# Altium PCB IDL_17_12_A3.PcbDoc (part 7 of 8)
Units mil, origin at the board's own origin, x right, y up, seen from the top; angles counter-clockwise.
Board outline 5119.97 x 10350 mil, 6 copper layers (Top Signal, 3.3 Volt, GND, 5 Volt, Split Plane, Bot Signal), stack 66.2 mil thick; 510 components, 178 nets, 2317 pads, 385 vias.
Unrouted connection lines stored in the file: 1.
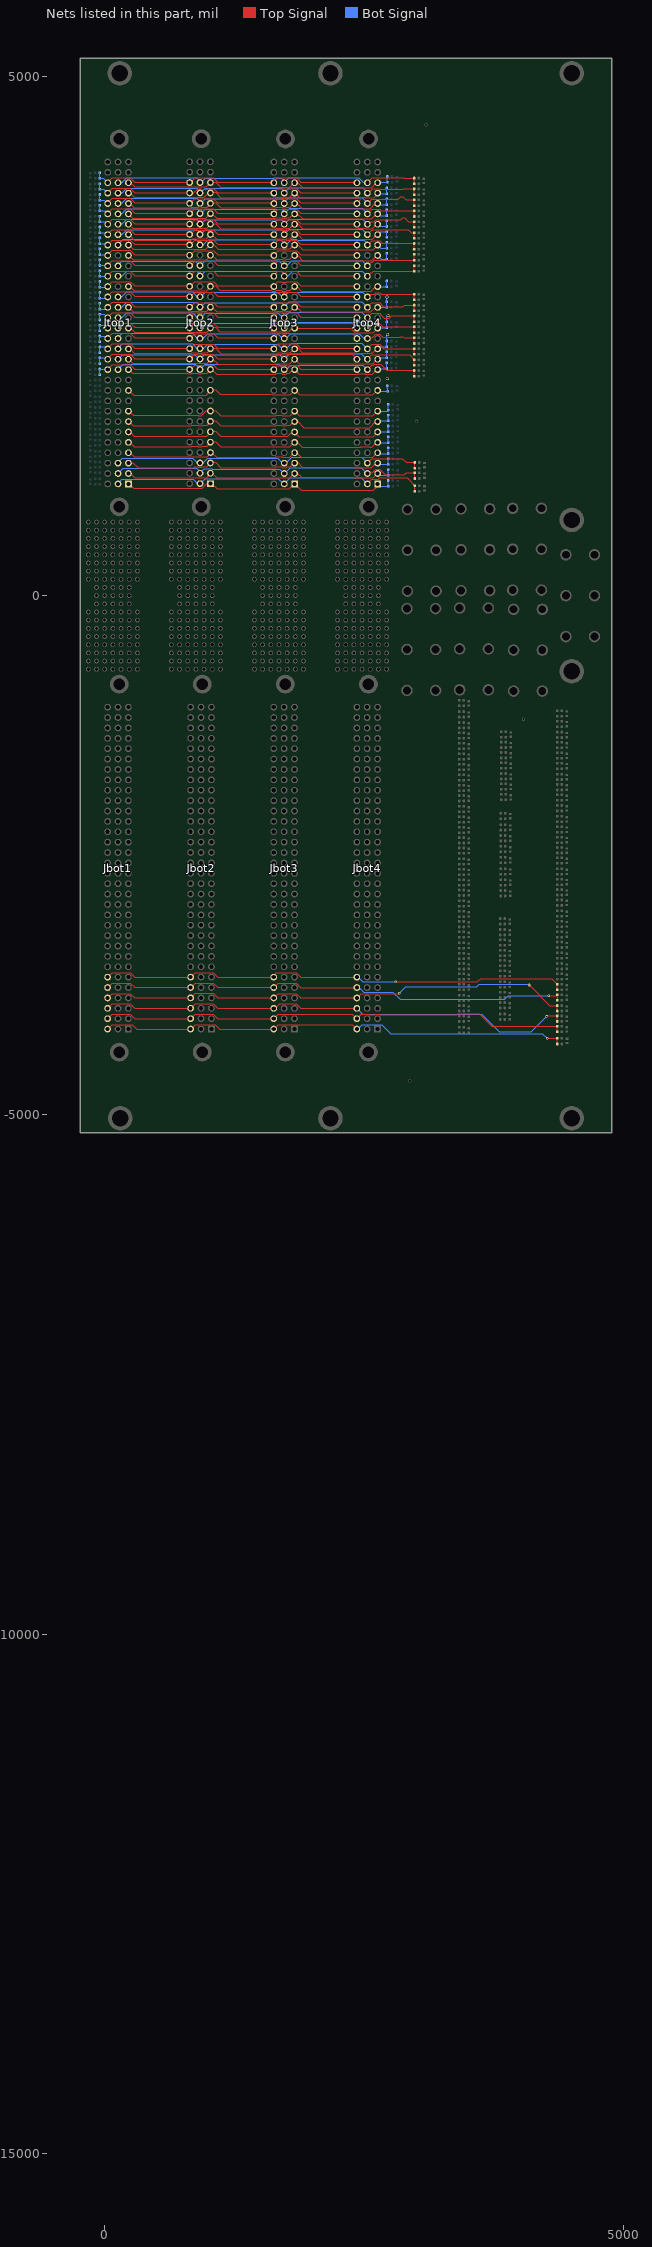
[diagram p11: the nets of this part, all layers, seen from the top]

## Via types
v1: diameter 25.59, hole 11.81, Top Signal to Bot Signal, 385 vias

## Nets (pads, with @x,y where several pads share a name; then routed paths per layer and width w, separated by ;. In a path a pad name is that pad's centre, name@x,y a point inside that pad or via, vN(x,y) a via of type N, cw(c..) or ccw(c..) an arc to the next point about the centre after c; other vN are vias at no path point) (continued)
JB84: Jbot1.C6 Jbot2.C6 Jbot3.C6 Jbot4.C6 R1RB_IDL_17_12_TerB84.1 R2RB_IDL_17_12_TerB84.2 | length 4543.9
  Top Signal w8: Jbot1.C6@28.26,-3673.77 70.74,-3631.29 245.86,-3631.29 287.92,-3673.35 Jbot2.C6@828.19,-3673.35 871.01,-3630.52 1045.44,-3630.52 1088.27,-3673.35 1608.49,-3673.35 1618.13,-3663.7 1650.55,-3631.29 1845.79,-3631.29 1888.27,-3673.77 Jbot4.C6@2428.19,-3673.77 ; v1(2802.08,-3719.17) 3550.2,-3719.17 3550.68,-3718.69 3586.72,-3718.69 3587.94,-3719.9 3620.16,-3687.68 3748.83,-3687.68 3749.35,-3688.2 4304.11,-3688.2 R1RB_IDL_17_12_TerB84.1@4358.16,-3742.25 4358.16,-3768.94 4358.67,-3769.46 R2RB_IDL_17_12_TerB84.2@4358.67,-3795.11
  Bot Signal w8: Jbot4.C6@2428.19,-3673.77 2442.94,-3673.77 2486.46,-3717.29 2800.2,-3717.29 v1(2802.08,-3719.17)
JB85: Jbot1.C5 Jbot2.C5 Jbot3.C5 Jbot4.C5 R1RB_IDL_17_12_TerB85.1 R2RB_IDL_17_12_TerB85.2 | length 4551
  Top Signal w8: Jbot1.C5@28.26,-3773.77 70.74,-3731.29 245.86,-3731.29 287.92,-3773.35 Jbot2.C5@828.19,-3773.35 870.67,-3730.87 1045.79,-3730.87 1088.27,-3773.35 1627.77,-3773.35 Jbot3.C5@1628.19,-3773.77 1670.67,-3731.29 1845.79,-3731.29 1888.27,-3773.77 Jbot4.C5@2428.19,-3773.77 ; v1(4275.93,-3852.46) R1RB_IDL_17_12_TerB85.1@4358.16,-3852.46 ; R1RB_IDL_17_12_TerB85.1@4358.16,-3842.25 R1RB_IDL_17_12_TerB85.1@4358.16,-3852.46 ; R2RB_IDL_17_12_TerB85.2@4358.67,-3895.11 4358.16,-3868.94 R1RB_IDL_17_12_TerB85.1@4358.16,-3852.46
  Bot Signal w8: Jbot4.C5@2428.19,-3773.77 2451.37,-3773.77 2497.23,-3819.62 2774.9,-3819.62 2844.07,-3888.8 3851.52,-3888.8 3887.86,-3852.46 v1(4275.93,-3852.46)
JB86: Jbot1.C4 Jbot2.C4 Jbot3.C4 Jbot4.C4 R1RB_IDL_17_12_TerB86.1 R2RB_IDL_17_12_TerB86.2 | length 4630.8
  Top Signal w8: Jbot1.C4@28.26,-3873.77 70.74,-3831.29 245.86,-3831.29 287.92,-3873.35 Jbot2.C4@828.19,-3873.35 870.67,-3830.87 1045.79,-3830.87 1088.27,-3873.35 1627.77,-3873.35 Jbot3.C4@1628.19,-3873.77 1670.67,-3831.29 1845.79,-3831.29 1888.27,-3873.77 Jbot4.C4@2428.19,-3873.77 2470.67,-3831.29 2834.4,-3831.29 v1(2836.02,-3829.66) ; v1(4087.23,-3750) 4100.68,-3763.46 4101.89,-3763.46 4285.68,-3947.25 R1RB_IDL_17_12_TerB86.1@4358.16,-3947.25 4358.16,-3973.94 4358.67,-3974.46 R2RB_IDL_17_12_TerB86.2@4358.67,-4000.11
  Bot Signal w8: v1(2836.02,-3829.66) 2836.02,-3827.35 2899.09,-3764.28 3582.92,-3764.28 3606.76,-3740.44 4077.66,-3740.44 v1(4087.23,-3750)
JB87: Jbot1.C3 Jbot2.C3 Jbot3.C3 Jbot4.C3 R1RB_IDL_17_12_TerB87.1 R2RB_IDL_17_12_TerB87.2 | length 4645
  Top Signal w8: Jbot1.C3@28.26,-3973.77 70.74,-3931.29 245.86,-3931.29 287.92,-3973.35 Jbot2.C3@828.19,-3973.35 870.67,-3930.87 1045.79,-3930.87 1088.27,-3973.35 1627.77,-3973.35 Jbot3.C3@1628.19,-3973.77 1642.67,-3973.77 1685.9,-3930.53 ; 1685.9,-3930.25 1844.68,-3930.25 ; 1844.68,-3930.18 1888.27,-3973.77 Jbot4.C3@2428.19,-3973.77 ; v1(4256.68,-4051.46) 4260.89,-4047.25 R1RB_IDL_17_12_TerB87.1@4358.16,-4047.25 4358.16,-4099.6 R2RB_IDL_17_12_TerB87.2@4358.67,-4100.11
  Bot Signal w8: Jbot4.C3@2428.19,-3973.77 2485.71,-4031.29 3631.64,-4031.29 3798.81,-4198.46 4109.68,-4198.46 v1(4256.68,-4051.46)
JB88: Jbot1.C2 Jbot2.C2 Jbot3.C2 Jbot4.C2 R1RB_IDL_17_12_TerB88.1 R2RB_IDL_17_12_TerB88.2 | length 4564.8
  Top Signal w8: Jbot1.C2@28.26,-4073.77 70.74,-4031.29 245.86,-4031.29 287.92,-4073.35 Jbot2.C2@828.19,-4073.35 870.67,-4030.87 1045.79,-4030.87 1088.27,-4073.35 1627.77,-4073.35 Jbot3.C2@1628.19,-4073.77 1670.67,-4031.29 2385.71,-4031.29 Jbot4.C2@2428.19,-4073.77 2470.67,-4031.29 2545.78,-4031.29 2548.82,-4034.32 2607.56,-4034.32 2610.59,-4031.29 2645.78,-4031.29 2648.82,-4034.32 3392.18,-4034.32 3401.98,-4024.51 3607.12,-4024.51 3729.86,-4147.25 R1RB_IDL_17_12_TerB88.1@4358.16,-4147.25 4358.16,-4173.94 4358.67,-4174.46 R2RB_IDL_17_12_TerB88.2@4358.67,-4200.11
JB89: Jbot1.C1 Jbot2.C1 Jbot3.C1 Jbot4.C1 R1RB_IDL_17_12_TerB89.1 R2RB_IDL_17_12_TerB89.2 | length 4564.4
  Top Signal w8: Jbot1.C1@28.26,-4173.77 70.74,-4131.29 264.88,-4131.29 306.94,-4173.35 Jbot2.C1@828.19,-4173.35 870.67,-4130.87 1064.81,-4130.87 1107.29,-4173.35 1627.77,-4173.35 Jbot3.C1@1628.19,-4173.77 1670.67,-4131.29 2385.71,-4131.29 Jbot4.C1@2428.19,-4173.77 ; v1(4261.68,-4262.25) R1RB_IDL_17_12_TerB89.1@4360.11,-4262.25 4360.11,-4290.42 ; R2RB_IDL_17_12_TerB89.2@4360.08,-4317.34 4360.08,-4290.46
  Bot Signal w8: Jbot4.C1@2428.19,-4173.77 2436.88,-4173.77 2479.36,-4131.29 2670.67,-4131.29 2755.84,-4216.46 4215.89,-4216.46 v1(4261.68,-4262.25)
JT1: Jtop1.A30 Jtop2.A30 Jtop3.A30 Jtop4.A30 R1R_IDL_17_12_TerA1.1 R2R_IDL_17_12_TerA1.2 | length 2671.5
  Top Signal w8: Jtop1.A30@228.79,3982.06 241.96,3982.06 288.16,3935.87 978.39,3935.87 1018.19,3975.66 Jtop2.A30@1018.19,3978.35 ; Jtop2.A30@1018.19,3982.48 1068.16,3982.48 1116.89,3933.76 1646.87,3933.76 1648.28,3935.16 1710.28,3935.16 1711.68,3933.76 1780.41,3933.76 Jtop3.A30@1826.02,3979.37 ; Jtop3.A30@1815.98,3979.37 Jtop3.A30@1826.02,3979.37 ; Jtop3.A30@1828.72,3982.06 Jtop3.A30@1826.02,3979.37 ; Jtop4.A30@2615.98,3973.83 2570.47,3928.31 1907.31,3928.31 1856.26,3979.37 Jtop3.A30@1826.02,3979.37
  Bot Signal w8: Jtop4.A30@2629.28,3976.24 2634.94,3981.9 R2R_IDL_17_12_TerA1.2@2723.46,3981.9 2722.58,3982.77 R1R_IDL_17_12_TerA1.1@2722.58,4036.92
JT2: Jtop1.A29 Jtop2.A29 Jtop3.A29 Jtop4.A29 R1R_IDL_17_12_TerA2.1 R2R_IDL_17_12_TerA2.2 | length 2662.6
  Top Signal w8: Jtop1.A29@228.79,3882.06 Jtop1.A29@229.28,3882.06 ; Jtop1.A29@229.28,3876.24 245.63,3876.24 286,3835.87 835.78,3835.87 837.4,3837.48 898.98,3837.48 900.59,3835.87 935.78,3835.87 937.4,3837.48 960.44,3837.48 1001.31,3878.35 Jtop2.A29@1018.19,3878.35 ; Jtop2.A29@1028.72,3882.48 1068.16,3882.48 1116.89,3833.76 1646.87,3833.76 1649.86,3836.75 1708.69,3836.75 1711.68,3833.76 1746.87,3833.76 1749.86,3836.75 1783.4,3836.75 1828.72,3882.06 1877.03,3833.76 2446.87,3833.76 2447.33,3834.21 2511.23,3834.21 2511.68,3833.76 2597.53,3833.76 Jtop4.A29@2639.15,3875.37
  Bot Signal w8: Jtop4.A29@2629.28,3876.24 2634.85,3870.66 R2R_IDL_17_12_TerA2.2@2718.46,3870.66 2717.58,3871.54 R1R_IDL_17_12_TerA2.1@2717.58,3925.68
JT3: Jtop1.A28 Jtop2.A28 Jtop3.A28 Jtop4.A28 R1R_IDL_17_12_TerA3.1 R2R_IDL_17_12_TerA3.2 | length 2692.8
  Top Signal w8: Jtop1.A28@228.79,3782.06 237.3,3782.06 283.5,3735.87 835.78,3735.87 839.92,3740 896.46,3740 900.59,3735.87 935.78,3735.87 939.92,3740 986.24,3740 1028.72,3782.48 1068.16,3782.48 1116.89,3733.76 1646.87,3733.76 1651.44,3738.32 1707.12,3738.32 1711.68,3733.76 1746.87,3733.76 1751.44,3738.32 1784.98,3738.32 Jtop3.A28@1828.72,3782.06 ; Jtop3.A28@1806.71,3782.46 1846.99,3782.46 1901.62,3727.83 2557.62,3727.83 Jtop4.A28@2606.71,3776.92 ; Jtop4.A28@2629.28,3776.24 Jtop4.A28@2639.94,3765.57
  Bot Signal w8: Jtop4.A28@2629.28,3776.24 2639.85,3765.66 R2R_IDL_17_12_TerA3.2@2718.46,3765.66 2718.46,3819.81 R1R_IDL_17_12_TerA3.1@2717.58,3820.68
JT4: Jtop1.A27 Jtop2.A27 Jtop3.A27 Jtop4.A27 R1R_IDL_17_12_TerA4.1 R2R_IDL_17_12_TerA4.2 | length 2680.8
  Top Signal w8: Jtop1.A27@228.79,3682.06 Jtop1.A27@229.28,3682.06 ; Jtop1.A27@229.28,3676.24 270.54,3634.97 974.81,3634.97 Jtop2.A27@1018.19,3678.35 ; Jtop2.A27@1028.72,3682.48 1077.45,3633.76 1646.87,3633.76 1650.52,3637.4 1708.04,3637.4 1711.68,3633.76 1746.87,3633.76 1750.52,3637.4 1784.06,3637.4 Jtop3.A27@1826.59,3679.93 ; Jtop3.A27@1815.66,3679.93 Jtop3.A27@1826.59,3679.93 ; Jtop3.A27@1828.72,3682.06 Jtop3.A27@1826.59,3679.93 ; Jtop4.A27@2615.66,3674.39 2570.25,3628.98 1906.89,3628.98 1855.94,3679.93 Jtop3.A27@1826.59,3679.93 ; Jtop4.A27@2629.28,3676.24 Jtop4.A27@2644.94,3660.57
  Bot Signal w8: Jtop4.A27@2629.28,3676.24 2644.85,3660.66 R2R_IDL_17_12_TerA4.2@2718.46,3660.66 2718.46,3714.81 R1R_IDL_17_12_TerA4.1@2717.58,3715.68
JT5: Jtop1.A26 Jtop2.A26 Jtop3.A26 Jtop4.A26 R1R_IDL_17_12_TerA5.1 R2R_IDL_17_12_TerA5.2 | length 2704.3
  Top Signal w8: Jtop1.A26@228.79,3582.06 Jtop1.A26@229.28,3582.06 ; Jtop1.A26@229.28,3576.24 269.65,3535.87 835.78,3535.87 838.26,3538.34 898.12,3538.34 900.59,3535.87 982.1,3535.87 1028.72,3582.48 1068.16,3582.48 1116.89,3533.76 1646.87,3533.76 1650.85,3537.73 1707.71,3537.73 1711.68,3533.76 1746.87,3533.76 1750.85,3537.73 1784.39,3537.73 Jtop3.A26@1828.72,3582.06 ; Jtop3.A26@1819.89,3583.13 1860.17,3583.13 1909.54,3533.76 2446.87,3533.76 2449.11,3535.99 2509.44,3535.99 2511.68,3533.76 2576.06,3533.76 Jtop4.A26@2619.89,3577.59 ; Jtop4.A26@2629.28,3576.24 Jtop4.A26@2649.94,3555.57
  Bot Signal w8: Jtop4.A26@2629.28,3576.24 2649.85,3555.66 R2R_IDL_17_12_TerA5.2@2718.46,3555.66 2718.46,3609.81 R1R_IDL_17_12_TerA5.1@2717.58,3610.68
JT6: Jtop1.A25 Jtop2.A25 Jtop3.A25 Jtop4.A25 R1R_IDL_17_12_TerA6.1 R2R_IDL_17_12_TerA6.2 | length 2685.1
  Top Signal w8: Jtop1.A25@228.79,3482.06 231.95,3478.91 290.99,3419.86 291.95,3420.83 834.76,3420.83 849.8,3435.87 935.78,3435.87 937.07,3437.15 977,3437.15 Jtop2.A25@1018.19,3478.35 ; Jtop2.A25@1028.72,3482.48 1077.45,3433.76 1646.87,3433.76 1651.93,3438.81 1706.63,3438.81 1711.68,3433.76 1746.87,3433.76 1751.93,3438.81 1785.47,3438.81 Jtop3.A25@1826.93,3480.27 ; Jtop3.A25@1816.87,3480.27 Jtop3.A25@1826.93,3480.27 ; Jtop3.A25@1828.72,3482.06 Jtop3.A25@1826.93,3480.27 ; Jtop4.A25@2616.87,3474.73 2575.9,3433.76 1903.66,3433.76 1857.15,3480.27 Jtop3.A25@1826.93,3480.27 ; Jtop4.A25@2629.28,3476.24 Jtop4.A25@2635.77,3469.75
  Bot Signal w8: Jtop4.A25@2629.28,3476.24 2658.72,3505.68 R1R_IDL_17_12_TerA6.1@2717.58,3505.68 2717.58,3451.54 R2R_IDL_17_12_TerA6.2@2718.46,3450.66
JT7: Jtop1.A24 Jtop2.A24 Jtop3.A24 Jtop4.A24 R1R_IDL_17_12_TerA7.1 R2R_IDL_17_12_TerA7.2 | length 2699.8
  Top Signal w8: Jtop1.A24@228.79,3382.06 274.99,3335.87 975.71,3335.87 Jtop2.A24@1018.19,3378.35 1018.19,3371.95 1028.72,3382.48 1044.58,3382.48 1093.31,3333.76 1646.87,3333.76 1652.76,3339.64 1705.8,3339.64 1711.68,3333.76 1746.87,3333.76 1752.76,3339.64 1786.3,3339.64 Jtop3.A24@1827.7,3381.04 ; Jtop3.A24@1818.68,3381.04 Jtop3.A24@1827.7,3381.04 ; Jtop3.A24@1828.72,3382.06 Jtop3.A24@1827.7,3381.04 ; Jtop4.A24@2629.28,3376.24 2584.05,3331.01 1909,3331.01 1858.96,3381.04 Jtop3.A24@1827.7,3381.04
  Bot Signal w8: Jtop4.A24@2629.28,3376.24 2659.85,3345.66 R2R_IDL_17_12_TerA7.2@2718.46,3345.66 2717.58,3346.54 R1R_IDL_17_12_TerA7.1@2717.58,3400.68
JT8: Jtop1.A23 Jtop2.A23 Jtop3.A23 Jtop4.A23 R1R_IDL_17_12_TerA8.1 R2R_IDL_17_12_TerA8.2 | length 2714.9
  Top Signal w8: Jtop1.A23@228.79,3282.06 274.99,3235.87 835.78,3235.87 836.16,3236.25 900.21,3236.25 900.59,3235.87 982.1,3235.87 1028.72,3282.48 1077.45,3233.76 1646.87,3233.76 1651.09,3237.97 1707.47,3237.97 1711.68,3233.76 1746.87,3233.76 1751.09,3237.97 1784.63,3237.97 Jtop3.A23@1824.24,3277.58 ; Jtop3.A23@1817.47,3277.58 Jtop3.A23@1824.24,3277.58 ; Jtop3.A23@1828.72,3282.06 Jtop3.A23@1824.24,3277.58 ; Jtop4.A23@2641.02,3295.59 2572.07,3226.63 1908.7,3226.63 1857.75,3277.58 Jtop3.A23@1824.24,3277.58
  Bot Signal w8: Jtop4.A23@2629.28,3276.24 2664.85,3240.66 R2R_IDL_17_12_TerA8.2@2718.46,3240.66 2718.46,3267.09 2717.58,3267.97 R1R_IDL_17_12_TerA8.1@2717.58,3295.68
JT9: Jtop1.A20 Jtop2.A20 Jtop3.A20 Jtop4.A20 R1R_IDL_17_12_TerA9.1 R2R_IDL_17_12_TerA9.2 | length 2668.1
  Top Signal w8: Jtop1.A20@228.79,2982.06 238.83,2982.06 285.02,2935.87 835.78,2935.87 837.51,2937.59 898.87,2937.59 900.59,2935.87 935.78,2935.87 937.51,2937.59 983.83,2937.59 1028.72,2982.48 1068.16,2982.48 1109.69,2940.95 1604.49,2940.95 1611.68,2933.76 1646.87,2933.76 1654.07,2940.95 1704.49,2940.95 1711.68,2933.76 1746.87,2933.76 1754.07,2940.95 1787.61,2940.95 Jtop3.A20@1825.96,2979.3 ; Jtop3.A20@1807.79,2979.3 Jtop3.A20@1825.96,2979.3 ; Jtop3.A20@1828.72,2982.06 Jtop3.A20@1825.96,2979.3 ; Jtop4.A20@2607.79,2973.76 2566.59,2932.55 1894.82,2932.55 1848.07,2979.3 Jtop3.A20@1825.96,2979.3 ; Jtop4.A20@2629.28,2976.24 Jtop4.A20@2629.94,2975.57
  Bot Signal w8: Jtop4.A20@2629.28,2976.24 2629.85,2975.66 R2R_IDL_17_12_TerA9.2@2718.46,2975.66 2718.46,3002.09 2717.58,3002.97 R1R_IDL_17_12_TerA9.1@2717.58,3030.68
JT10: AS.1 Jtop1.A18 Jtop2.A18 Jtop3.A18 Jtop4.A18 R1R_IDL_17_12_TerA10.1 R2R_IDL_17_12_TerA10.2 | length 2713
  Top Signal w8: Jtop1.A18@228.79,2782.06 274.99,2735.87 835.78,2735.87 836.67,2736.76 899.7,2736.76 900.59,2735.87 935.78,2735.87 936.67,2736.76 982.99,2736.76 1028.72,2782.48 1077.45,2733.76 1646.87,2733.76 1652.99,2739.87 1705.57,2739.87 1711.68,2733.76 1746.87,2733.76 1752.99,2739.87 1786.53,2739.87 Jtop3.A18@1826.9,2780.24 ; Jtop3.A18@1805.37,2780.24 Jtop3.A18@1826.9,2780.24 ; Jtop3.A18@1828.72,2782.06 Jtop3.A18@1826.9,2780.24 ; Jtop4.A18@2605.37,2774.7 2564.43,2733.76 2511.68,2733.76 2510,2735.44 2448.56,2735.44 2446.87,2733.76 1892.14,2733.76 1845.65,2780.24 Jtop3.A18@1826.9,2780.24 ; Jtop4.A18@2629.28,2776.24 Jtop4.A18@2629.94,2775.57
  Bot Signal w8: Jtop4.A18@2629.28,2776.24 2629.85,2775.66 R2R_IDL_17_12_TerA10.2@2718.46,2775.66 2718.46,2802.09 2717.58,2802.97 R1R_IDL_17_12_TerA10.1@2717.58,2830.68 AS.1@2717.58,2875.93
JT11: DTACK.1 Jtop1.A16 Jtop2.A16 Jtop3.A16 Jtop4.A16 R1R_IDL_17_12_TerA11.1 R2R_IDL_17_12_TerA11.2 | length 2739.3
  Top Signal w8: Jtop1.A16@228.79,2582.06 242.31,2582.06 288.51,2535.87 835.78,2535.87 835.94,2536.02 900.44,2536.02 900.59,2535.87 982.1,2535.87 1028.72,2582.48 1069,2582.48 1108.96,2542.52 1602.92,2542.52 1611.68,2533.76 1646.87,2533.76 1655.64,2542.52 1702.92,2542.52 1711.68,2533.76 1746.87,2533.76 1754.83,2541.71 1771.16,2541.71 1805.69,2576.24 2367.9,2576.24 2412.85,2531.29 2584.33,2531.29 Jtop4.A16@2633.62,2580.57
  Bot Signal w8: Jtop4.A16@2629.28,2576.24 2633.7,2580.66 R2R_IDL_17_12_TerA11.2@2718.46,2580.66 2717.58,2581.54 R1R_IDL_17_12_TerA11.1@2717.58,2635.68 2717.58,2684.07 DTACK.1@2729.61,2696.1
JT12: Jtop1.A14 Jtop2.A14 Jtop3.A14 Jtop4.A14 R1R_IDL_17_12_TerA12.1 R2R_IDL_17_12_TerA12.2 WRITE.1 | length 2754.2
  Top Signal w8: Jtop1.A14@228.79,2382.06 239.95,2382.06 286.15,2335.87 835.78,2335.87 839.92,2340 896.46,2340 900.59,2335.87 935.78,2335.87 939.92,2340 986.24,2340 1028.72,2382.48 1069,2382.48 1120.52,2330.97 1657.83,2330.97 1666.44,2339.58 1705.86,2339.58 1711.68,2333.76 1746.87,2333.76 1752.7,2339.58 1786.24,2339.58 Jtop3.A14@1828.72,2382.06 ; Jtop3.A14@1818.29,2385.05 1858.56,2385.05 1904.03,2339.58 2405.86,2339.58 2411.68,2333.76 2446.87,2333.76 2449.84,2336.72 2508.72,2336.72 2511.68,2333.76 2567,2333.76 2574.31,2341.07 2579.84,2341.07 Jtop4.A14@2618.29,2379.51 ; Jtop4.A14@2629.28,2376.24 Jtop4.A14@2633.47,2380.43
  Bot Signal w8: Jtop4.A14@2629.28,2376.24 2650.49,2397.45 R2R_IDL_17_12_TerA12.2@2718.09,2397.45 2717.22,2398.32 R1R_IDL_17_12_TerA12.1@2717.22,2452.47 2717.22,2506.2 WRITE.1@2724.12,2513.11
JT13: Jtop1.A13 Jtop2.A13 Jtop3.A13 Jtop4.A13 R1R_IDL_17_12_TerA13.1 R2R_IDL_17_12_TerA13.2 | length 2684.7
  Top Signal w8: Jtop1.A13@228.79,2282.06 270.85,2240 796.46,2240 800.59,2235.87 835.78,2235.87 839.92,2240 896.46,2240 900.59,2235.87 935.78,2235.87 939.92,2240 986.24,2240 1028.72,2282.48 1038.36,2282.48 1091.54,2229.3 1646.32,2229.3 1650.77,2233.76 1780.41,2233.76 Jtop3.A13@1826.09,2279.43 ; Jtop3.A13@1829.28,2276.24 1872.53,2232.99 2581.09,2232.99 Jtop4.A13@2623,2274.9 ; Jtop4.A13@2629.28,2276.24 Jtop4.A13@2645.4,2292.36
  Bot Signal w8: Jtop4.A13@2629.28,2276.24 2645.49,2292.45 R2R_IDL_17_12_TerA13.2@2718.09,2292.45 2717.22,2293.32 R1R_IDL_17_12_TerA13.1@2717.22,2347.47
JT14: Jtop1.A12 Jtop2.A12 Jtop3.A12 Jtop4.A12 R1R_IDL_17_12_TerA14.1 R2R_IDL_17_12_TerA14.2 | length 2688.5
  Top Signal w8: Jtop1.A12@228.79,2182.06 270.85,2140 796.46,2140 800.59,2135.87 835.78,2135.87 839.92,2140 896.46,2140 900.59,2135.87 935.78,2135.87 939.92,2140 986.24,2140 1028.72,2182.48 1077.45,2133.76 1646.87,2133.76 1653.34,2140.22 1705.22,2140.22 1711.68,2133.76 1746.87,2133.76 1753.34,2140.22 1779.44,2140.22 1815.46,2176.24 Jtop3.A12@1829.28,2176.24 1871.76,2133.76 2446.87,2133.76 2449.86,2136.74 2508.7,2136.74 2511.68,2133.76 2578.6,2133.76 Jtop4.A12@2623,2178.16 ; Jtop3.A12@1823,2183.7 Jtop3.A12@1829.28,2183.7 ; Jtop4.A12@2629.28,2176.24 Jtop4.A12@2640.4,2187.36
  Bot Signal w8: Jtop4.A12@2629.28,2176.24 2640.49,2187.45 R2R_IDL_17_12_TerA14.2@2718.09,2187.45 2718.09,2214.09 2717.22,2214.97 R1R_IDL_17_12_TerA14.1@2717.22,2242.47
JT15: Jtop1.A10 Jtop2.A10 Jtop3.A10 Jtop4.A10 R1R_IDL_17_12_TerA15.1 R2R_IDL_17_12_TerA15.2 SYSCLK.1 | length 2678.9
  Top Signal w8: Jtop1.A10@228.79,1982.06 280.9,1929.96 976.19,1929.96 1028.72,1982.48 1069,1982.48 1111.9,1939.58 1605.86,1939.58 1611.68,1933.76 1787.73,1933.76 1832.38,1978.41 1878.1,1932.69 2583.61,1932.69 Jtop4.A10@2623.79,1972.87 ; Jtop4.A10@2629.28,1976.24 Jtop4.A10@2638.1,1967.42
  Bot Signal w8: Jtop4.A10@2629.28,1976.24 2638.01,1967.51 R2R_IDL_17_12_TerA15.2@2724.1,1967.51 2724.1,1994.09 2723.22,1994.97 R1R_IDL_17_12_TerA15.1@2723.22,2022.53
JT16: Jtop1.A8 Jtop2.A8 Jtop3.A8 Jtop4.A8 R1R_IDL_17_12_TerA16.1 R2R_IDL_17_12_TerA16.2 | length 2680
  Top Signal w8: Jtop1.A8@228.79,1782.06 274.99,1735.87 900.53,1735.87 ; 900.56,1735.9 901.63,1734.83 934.75,1734.83 ; 935.78,1735.87 978.27,1778.35 Jtop2.A8@1018.19,1778.35 ; Jtop2.A8@1018.19,1782.48 1069,1782.48 1117.73,1733.76 1646.87,1733.76 1652.68,1739.56 1705.88,1739.56 1711.68,1733.76 1786.77,1733.76 Jtop3.A8@1829.28,1776.26 ; Jtop3.A8@1823,1776.26 Jtop3.A8@1829.28,1776.26 ; Jtop3.A8@1826.09,1779.43 Jtop3.A8@1828.72,1782.06 ; Jtop4.A8@2623,1770.72 2583.21,1730.93 2554.46,1730.93 2552.67,1732.72 2505.88,1732.72 2504.09,1730.93 1874.62,1730.93 Jtop3.A8@1829.28,1776.26
  Bot Signal w8: Jtop4.A8@2629.28,1776.24 2719.23,1776.24 R2R_IDL_17_12_TerA16.2@2729.8,1786.8 2728.92,1787.68 R1R_IDL_17_12_TerA16.1@2728.92,1841.82
JT17: Jtop1.A7 Jtop2.A7 Jtop3.A7 Jtop4.A7 R1R_IDL_17_12_TerA17.1 R2R_IDL_17_12_TerA17.2 | length 2722.9
  Top Signal w8: Jtop1.A7@228.79,1682.06 274.99,1635.87 835.78,1635.87 839.23,1639.31 897.15,1639.31 900.59,1635.87 935.78,1635.87 939.92,1640 986.24,1640 1028.72,1682.48 1069,1682.48 1117.73,1633.76 1646.87,1633.76 1652.68,1639.56 1705.88,1639.56 1711.68,1633.76 1746.87,1633.76 1752.68,1639.56 1786.21,1639.56 Jtop3.A7@1828.72,1682.06 ; Jtop3.A7@1811.99,1682.66 1852.27,1682.66 1916.34,1618.59 2411.56,1618.59 2411.68,1618.72 2446.87,1618.72 2447,1618.59 2511.56,1618.59 2511.68,1618.72 2546.87,1618.72 2547,1618.59 2553.46,1618.59 Jtop4.A7@2611.99,1677.12 ; Jtop4.A7@2629.28,1676.24 Jtop4.A7@2648.1,1695.05
  Bot Signal w8: Jtop4.A7@2629.28,1676.24 2636.85,1683.8 R2R_IDL_17_12_TerA17.2@2729.8,1683.8 2729.8,1710.76 2728.92,1711.64 R1R_IDL_17_12_TerA17.1@2728.92,1738.82
JT18: Jtop1.A6 Jtop2.A6 Jtop3.A6 Jtop4.A6 R1R_IDL_17_12_TerA18.1 R2R_IDL_17_12_TerA18.2 | length 2683.1
  Top Signal w8: Jtop1.A6@228.79,1582.06 241.05,1582.06 287.24,1535.87 835.78,1535.87 836.53,1536.61 899.85,1536.61 900.59,1535.87 982.1,1535.87 1028.72,1582.48 1069,1582.48 1117.73,1533.76 1646.87,1533.76 1649.36,1536.24 1709.2,1536.24 1711.68,1533.76 1764.22,1533.76 1806.7,1576.24 Jtop3.A6@1829.28,1576.24 ; Jtop3.A6@1828.72,1574.12 1871.2,1531.64 2586.06,1531.64 Jtop4.A6@2623,1568.58 ; Jtop4.A6@2629.28,1576.24 Jtop4.A6@2643.1,1590.05
  Bot Signal w8: Jtop4.A6@2629.28,1576.24 2631.85,1578.8 R2R_IDL_17_12_TerA18.2@2729.8,1578.8 2729.8,1605.76 2728.92,1606.64 R1R_IDL_17_12_TerA18.1@2728.92,1633.82
JT19: Jtop1.A5 Jtop2.A5 Jtop3.A5 Jtop4.A5 R1R_IDL_17_12_TerA19.1 R2R_IDL_17_12_TerA19.2 | length 2690.3
  Top Signal w8: Jtop1.A5@228.79,1482.06 236.94,1482.06 283.13,1435.87 835.78,1435.87 839.92,1440 896.46,1440 900.59,1435.87 935.78,1435.87 939.92,1440 986.24,1440 1028.72,1482.48 1069,1482.48 1117.73,1433.76 1646.87,1433.76 1647.9,1434.78 1710.66,1434.78 1711.68,1433.76 1780.41,1433.76 Jtop3.A5@1824.03,1477.37 ; Jtop3.A5@1815.14,1477.37 Jtop3.A5@1824.03,1477.37 ; Jtop3.A5@1828.72,1482.06 Jtop3.A5@1824.03,1477.37 ; Jtop4.A5@2615.14,1471.83 2573.96,1430.66 2554.73,1430.66 2552.67,1432.72 2465.96,1432.72 2463.9,1430.66 1902.13,1430.66 1855.42,1477.37 Jtop3.A5@1824.03,1477.37 ; Jtop4.A5@2629.28,1476.24 Jtop4.A5@2638.1,1485.05
  Bot Signal w8: Jtop4.A5@2629.28,1476.24 2631.71,1473.8 R2R_IDL_17_12_TerA19.2@2729.8,1473.8 2729.8,1500.76 2728.92,1501.64 R1R_IDL_17_12_TerA19.1@2728.92,1528.82
JT20: Jtop1.A4 Jtop2.A4 Jtop3.A4 Jtop4.A4 R1R_IDL_17_12_TerA20.1 R2R_IDL_17_12_TerA20.2 | length 2685.1
  Top Signal w8: Jtop1.A4@228.79,1382.06 238.26,1382.06 284.45,1335.87 835.78,1335.87 839.92,1340 896.46,1340 900.59,1335.87 935.78,1335.87 939.92,1340 986.24,1340 1028.72,1382.48 1077.45,1333.76 1646.87,1333.76 1648.66,1335.54 1709.9,1335.54 1711.68,1333.76 1780.41,1333.76 Jtop3.A4@1817.06,1370.4 ; Jtop3.A4@1814.35,1370.4 Jtop3.A4@1817.06,1370.4 ; Jtop3.A4@1828.72,1382.06 Jtop3.A4@1817.06,1370.4 ; Jtop4.A4@2614.35,1364.86 2583.01,1333.52 1891.52,1333.52 1854.63,1370.4 Jtop3.A4@1817.06,1370.4 ; Jtop4.A4@2629.28,1376.24 Jtop4.A4@2639.43,1386.39
  Bot Signal w8: Jtop4.A4@2629.28,1376.24 2636.71,1368.8 R2R_IDL_17_12_TerA20.2@2729.8,1368.8 2729.8,1422.95 R1R_IDL_17_12_TerA20.1@2728.92,1423.82
JT21: Jtop1.A3 Jtop2.A3 Jtop3.A3 Jtop4.A3 R1R_IDL_17_12_TerA21.1 R2R_IDL_17_12_TerA21.2 | length 2697.3
  Top Signal w8: Jtop1.A3@228.79,1282.06 269.07,1282.06 321.24,1229.89 856.33,1229.89 865.4,1238.96 897.5,1238.96 900.59,1235.87 935.78,1235.87 938.88,1238.96 985.2,1238.96 1028.72,1282.48 1069,1282.48 1117.73,1233.76 1646.87,1233.76 1654.16,1241.04 1704.4,1241.04 1711.68,1233.76 1746.87,1233.76 1752.7,1239.58 1786.24,1239.58 Jtop3.A3@1828.72,1282.06 ; Jtop3.A3@1816.71,1283.88 1856.99,1283.88 1902.33,1238.54 2392.04,1238.54 2400.72,1229.86 2568.23,1229.86 Jtop4.A3@2616.71,1278.34 ; Jtop4.A3@2629.28,1276.24 Jtop4.A3@2630.46,1275.05
  Bot Signal w8: Jtop4.A3@2629.28,1276.24 2641.71,1263.8 R2R_IDL_17_12_TerA21.2@2729.8,1263.8 2729.8,1290.76 2728.92,1291.64 R1R_IDL_17_12_TerA21.1@2728.92,1318.82
JT22: Jtop1.A2 Jtop2.A2 Jtop3.A2 Jtop4.A2 R1R_IDL_17_12_TerA22.1 R2R_IDL_17_12_TerA22.2 | length 2699.8
  Top Signal w8: Jtop1.A2@228.79,1182.06 243.29,1182.06 289.49,1135.87 835.78,1135.87 836.21,1136.29 900.16,1136.29 900.59,1135.87 982.1,1135.87 1028.72,1182.48 1077.69,1133.52 1780.18,1133.52 Jtop3.A2@1828.72,1182.06 ; Jtop3.A2@1810.42,1184.78 1850.7,1184.78 1896.93,1138.54 2392.04,1138.54 2396.83,1133.76 2586.8,1133.76 Jtop4.A2@2629.28,1176.24
  Bot Signal w8: Jtop4.A2@2629.28,1176.24 2646.71,1158.8 R2R_IDL_17_12_TerA22.2@2729.8,1158.8 2729.8,1185.76 2728.92,1186.64 R1R_IDL_17_12_TerA22.1@2728.92,1213.82
JT23: Jtop1.A1 Jtop2.A1 Jtop3.A1 Jtop4.A1 R1R_IDL_17_12_TerA23.1 R2R_IDL_17_12_TerA23.2 | length 2699.7
  Top Signal w8: Jtop1.A1@228.79,1082.06 229.21,1082.48 279.33,1032.36 938.68,1032.36 988.8,1082.48 1028.72,1082.48 1082.18,1029.03 1775.69,1029.03 Jtop3.A1@1826.09,1079.43 ; Jtop3.A1@1829.28,1076.24 1892.21,1013.3 2587.64,1013.3 Jtop4.A1@2624.58,1050.24 ; Jtop4.A1@2629.28,1076.24 Jtop4.A1@2640.46,1065.05
  Bot Signal w8: Jtop4.A1@2629.28,1076.24 2651.71,1053.8 R2R_IDL_17_12_TerA23.2@2729.8,1053.8 2729.8,1080.76 2728.92,1081.64 R1R_IDL_17_12_TerA23.1@2728.92,1108.82
JT24: Jtop1.B30 Jtop2.B30 Jtop3.B30 Jtop4.B30 R1R_IDL_17_12_TerA24.1 R2R_IDL_17_12_TerA24.2 | length 3061.5
  Top Signal w8: Jtop4.B30@2540.26,3976.24 Jtop4.B30@2529.28,3976.24 2575.93,4022.88 2877.81,4022.88 2879.33,4021.36 R1R_IDL_17_12_TerA24.1@2981.11,4021.36 2981.11,3993.65 2981.99,3992.77 R2R_IDL_17_12_TerA24.2@2981.99,3966.34
  Bot Signal w8: Jtop1.B30@128.79,3982.06 168.72,3982.06 211.2,4024.54 810.71,4024.54 811.13,4024.96 846.32,4024.96 846.74,4024.54 886.66,4024.54 928.72,3982.48 967.98,4021.74 1630.11,4021.74 ; 1630.53,4022.16 1665.73,4022.16 1666.15,4021.74 1706.07,4021.74 Jtop3.B30@1737.24,3990.58 ; Jtop3.B30@1728.72,3982.06 Jtop3.B30@1737.24,3990.58 ; Jtop3.B30@1748.13,3979.68 Jtop3.B30@1737.24,3990.58 ; Jtop4.B30@2528.72,3982.06 2488.8,3982.06 2446.32,4024.54 1771.2,4024.54 Jtop3.B30@1737.24,3990.58
JT25: Jtop1.B29 Jtop2.B29 Jtop3.B29 Jtop4.B29 R1R_IDL_17_12_TerA25.1 R2R_IDL_17_12_TerA25.2 | length 3039.7
  Top Signal w8: Jtop4.B29@2529.28,3876.24 2538.19,3876.24 2580.67,3918.72 2646.87,3918.72 2652.33,3913.27 2870.73,3913.27 2873.83,3916.36 R1R_IDL_17_12_TerA25.1@2981.11,3916.36 2981.11,3862.22 R2R_IDL_17_12_TerA25.2@2981.99,3861.34
  Bot Signal w8: Jtop1.B29@128.79,3882.06 168.72,3882.06 211.2,3924.54 810.71,3924.54 811.13,3924.96 846.32,3924.96 846.74,3924.54 886.66,3924.54 928.72,3882.48 967.98,3921.74 1630.11,3921.74 ; 1630.53,3922.16 1706.07,3922.16 ; 1706.07,3921.74 Jtop3.B29@1738.43,3889.39 ; Jtop3.B29@1728.72,3882.06 1731.1,3882.06 Jtop3.B29@1738.43,3889.39 ; Jtop4.B29@2528.72,3882.06 2483.94,3926.85 1775.88,3926.85 Jtop3.B29@1738.43,3889.39
JT26: Jtop1.B28 Jtop2.B28 Jtop3.B28 Jtop4.B28 R1R_IDL_17_12_TerA26.1 R2R_IDL_17_12_TerA26.2 | length 3061
  Top Signal w8: Jtop4.B28@2529.28,3776.24 2571.76,3818.72 2827.11,3818.72 2851.5,3843.11 2870.38,3843.11 2902.12,3811.36 R1R_IDL_17_12_TerA26.1@2981.11,3811.36 2981.11,3783.65 2981.99,3782.77 R2R_IDL_17_12_TerA26.2@2981.99,3756.34
  Bot Signal w8: Jtop1.B28@128.79,3782.06 168.72,3782.06 211.2,3824.54 810.71,3824.54 811.13,3824.96 846.32,3824.96 846.74,3824.54 886.66,3824.54 928.72,3782.48 967.98,3821.74 1630.11,3821.74 ; 1630.53,3822.16 1665.73,3822.16 1666.15,3821.74 1706.07,3821.74 Jtop3.B28@1735.2,3792.61 ; Jtop3.B28@1728.72,3782.06 1728.72,3786.13 Jtop3.B28@1735.2,3792.61 ; Jtop4.B28@2528.72,3782.06 2479.54,3831.24 1773.84,3831.24 Jtop3.B28@1735.2,3792.61
JT27: Jtop1.B27 Jtop2.B27 Jtop3.B27 Jtop4.B27 R1R_IDL_17_12_TerA27.1 R2R_IDL_17_12_TerA27.2 | length 3047.4
  Top Signal w8: Jtop4.B27@2529.28,3676.24 2571.76,3718.72 2646.87,3718.72 2659.23,3706.36 R1R_IDL_17_12_TerA27.1@2981.11,3706.36 2981.11,3678.65 2981.99,3677.77 R2R_IDL_17_12_TerA27.2@2981.99,3651.34
  Bot Signal w8: Jtop1.B27@128.79,3682.06 168.72,3682.06 211.2,3724.54 810.71,3724.54 811.13,3724.96 846.32,3724.96 846.74,3724.54 886.66,3724.54 928.72,3682.48 967.98,3721.74 1630.11,3721.74 ; 1630.53,3722.16 1665.73,3722.16 1666.15,3721.74 1706.07,3721.74 Jtop3.B27@1739.5,3688.32 ; Jtop3.B27@1728.72,3682.06 1733.24,3682.06 Jtop3.B27@1739.5,3688.32 ; Jtop4.B27@2528.72,3682.06 2478.57,3732.22 1783.4,3732.22 Jtop3.B27@1739.5,3688.32
JT28: Jtop1.B26 Jtop2.B26 Jtop3.B26 Jtop4.B26 R1R_IDL_17_12_TerA28.1 R2R_IDL_17_12_TerA28.2 | length 3059.4
  Top Signal w8: Jtop4.B26@2529.28,3576.24 2554.41,3601.36 2594.33,3601.36 2611.68,3618.72 2851.74,3618.72 2869.92,3636.9 2888.81,3636.9 2924.34,3601.36 R1R_IDL_17_12_TerA28.1@2981.11,3601.36 2981.99,3600.49 R2R_IDL_17_12_TerA28.2@2981.99,3546.34
  Bot Signal w8: Jtop1.B26@128.79,3582.06 168.72,3582.06 211.2,3624.54 810.71,3624.54 811.13,3624.96 846.32,3624.96 846.74,3624.54 886.66,3624.54 928.72,3582.48 967.98,3621.74 1630.11,3621.74 ; 1630.53,3622.16 1665.73,3622.16 1666.15,3621.74 1706.07,3621.74 Jtop3.B26@1739.69,3588.12 ; Jtop3.B26@1728.72,3582.06 1733.63,3582.06 Jtop3.B26@1739.69,3588.12 ; Jtop4.B26@2528.72,3582.06 2485.1,3625.69 1777.25,3625.69 Jtop3.B26@1739.69,3588.12
JT29: Jtop1.B25 Jtop2.B25 Jtop3.B25 Jtop4.B25 R1R_IDL_17_12_TerA29.1 R2R_IDL_17_12_TerA29.2 | length 3065.3
  Top Signal w8: Jtop4.B25@2529.28,3476.24 2572.8,3519.76 2581.86,3519.76 2585.12,3523.01 2924.12,3523.01 2950.77,3496.36 R1R_IDL_17_12_TerA29.1@2981.11,3496.36 2981.11,3468.65 2981.99,3467.77 R2R_IDL_17_12_TerA29.2@2981.99,3441.34
  Bot Signal w8: Jtop1.B25@128.79,3482.06 168.72,3482.06 211.62,3524.96 846.32,3524.96 847.16,3524.12 887.09,3524.12 928.72,3482.48 968.4,3522.16 1665.73,3522.16 1666.57,3521.32 1706.49,3521.32 Jtop3.B25@1737.24,3490.58 ; Jtop3.B25@1728.72,3482.06 Jtop3.B25@1737.24,3490.58 ; Jtop3.B25@1748.13,3479.68 Jtop3.B25@1737.24,3490.58 ; Jtop4.B25@2528.72,3482.06 2481.69,3529.09 1775.75,3529.09 Jtop3.B25@1737.24,3490.58
JT30: Jtop1.B24 Jtop2.B24 Jtop3.B24 Jtop4.B24 R1R_IDL_17_12_TerA30.1 R2R_IDL_17_12_TerA30.2 | length 3097
  Top Signal w8: Jtop4.B24@2529.28,3376.24 2571.76,3418.72 2646.87,3418.72 2674.23,3391.36 R1R_IDL_17_12_TerA30.1@2981.11,3391.36 2981.11,3363.65 2981.99,3362.77 R2R_IDL_17_12_TerA30.2@2981.99,3336.34 2962.03,3336.34
  Bot Signal w8: Jtop1.B24@128.79,3382.06 177.8,3431.07 874.76,3431.07 923.35,3382.48 Jtop2.B24@928.72,3382.48 ; Jtop2.B24@948.2,3379.26 997.21,3428.28 1694.17,3428.28 1742.76,3379.68 Jtop3.B24@1748.13,3379.68 ; Jtop3.B24@1756.8,3388.51 1805.81,3437.52 1807.92,3437.52 1811.68,3433.76 1846.88,3433.76 1858.28,3422.35 2498.83,3422.35 2537.11,3384.07 Jtop4.B24@2544.49,3376.69 ; Jtop4.B24@2529.28,3376.24 Jtop4.B24@2556.3,3376.24
JT31: Jtop1.B22 Jtop2.B22 Jtop3.B22 Jtop4.B22 R1R_IDL_17_12_TerA31.1 R2R_IDL_17_12_TerA31.2 | length 3054.4
  Top Signal w8: Jtop4.B22@2529.28,3176.24 2565.68,3212.63 2577.87,3212.63 2596.58,3231.34 R2R_IDL_17_12_TerA31.2@2981.99,3231.34 2981.99,3257.77 2981.11,3258.65 R1R_IDL_17_12_TerA31.1@2981.11,3286.36
  Bot Signal w8: Jtop1.B22@129.28,3176.24 129.28,3185.24 166.25,3222.2 874.33,3222.2 Jtop2.B22@918.19,3178.35 966.64,3226.8 1678.72,3226.8 Jtop3.B22@1729.28,3176.24 1754.32,3176.24 1802.58,3224.5 2481.02,3224.5 Jtop4.B22@2529.28,3176.24
JT32: Jtop1.B21 Jtop2.B21 Jtop3.B21 Jtop4.B21 R1R_IDL_17_12_TerA32.1 R2R_IDL_17_12_TerA32.2 | length 3050.9
  Top Signal w8: Jtop4.B21@2529.28,3076.24 2563.59,3110.54 2575.61,3110.54 2588.41,3123.34 R2R_IDL_17_12_TerA32.2@2981.99,3123.34 2981.11,3124.22 R1R_IDL_17_12_TerA32.1@2981.11,3178.36
  Bot Signal w8: Jtop1.B21@128.79,3082.06 168.72,3082.06 211.2,3124.54 810.71,3124.54 811.13,3124.96 886.24,3124.96 928.72,3082.48 967.98,3121.74 1630.11,3121.74 ; 1630.53,3122.16 1705.65,3122.16 Jtop3.B21@1745.75,3082.06 ; Jtop3.B21@1728.72,3082.06 Jtop3.B21@1745.75,3082.06 ; Jtop3.B21@1748.13,3079.68 Jtop3.B21@1745.75,3082.06 ; Jtop4.B21@2528.72,3082.06 2524.48,3082.06 2482,3124.54 1811.13,3124.54 1768.65,3082.06 Jtop3.B21@1745.75,3082.06
JT33: Jtop1.B19 Jtop2.B19 Jtop3.B19 Jtop4.B19 R1R_IDL_17_12_TerA33.1 R2R_IDL_17_12_TerA33.2 | length 3081.9
  Top Signal w8: Jtop4.B19@2529.28,2876.24 2556.41,2903.36 2596.33,2903.36 2611.68,2918.72 2646.87,2918.72 2662.23,2903.36 R1R_IDL_17_12_TerA33.1@2981.11,2903.36 2981.11,2849.22 R2R_IDL_17_12_TerA33.2@2981.99,2848.34
  Bot Signal w8: Jtop1.B19@128.79,2882.06 168.72,2882.06 211.2,2924.54 810.71,2924.54 811.13,2924.96 846.32,2924.96 888.8,2882.48 928.72,2882.48 967.98,2921.74 1630.11,2921.74 ; 1630.53,2922.16 1665.73,2922.16 1708.21,2879.68 Jtop3.B19@1748.13,2879.68 ; Jtop3.B19@1728.72,2882.06 1770.04,2923.38 2431.11,2923.38 2432.87,2921.62 2484.12,2921.62 2516.81,2888.93 2541.98,2888.93 Jtop4.B19@2529.28,2876.24
JT34: Jtop1.B18 Jtop2.B18 Jtop3.B18 Jtop4.B18 R1R_IDL_17_12_TerA34.1 R2R_IDL_17_12_TerA34.2 | length 3090.6
  Top Signal w8: Jtop4.B18@2529.28,2776.24 2571.76,2818.72 2646.87,2818.72 2684.3,2781.29 2872.81,2781.29 2889.88,2798.36 R1R_IDL_17_12_TerA34.1@2981.11,2798.36 2981.11,2770.65 2981.99,2769.77 R2R_IDL_17_12_TerA34.2@2981.99,2743.34
  Bot Signal w8: Jtop1.B18@128.79,2782.06 168.72,2782.06 211.2,2824.54 810.71,2824.54 811.13,2824.96 846.32,2824.96 846.74,2824.54 886.66,2824.54 928.72,2782.48 967.98,2821.74 1630.11,2821.74 ; 1630.53,2822.16 1665.73,2822.16 ; 1666.15,2821.74 1706.07,2821.74 Jtop3.B18@1737.24,2790.58 ; Jtop3.B18@1728.72,2782.06 Jtop3.B18@1737.24,2790.58 ; 2438.72,2830.99 1777.65,2830.99 Jtop3.B18@1737.24,2790.58 ; 2439.14,2831.41 2474.33,2831.41 ; 2474.75,2830.99 Jtop4.B18@2529.51,2776.24 ; Jtop4.B18@2529.28,2776.24 Jtop4.B18@2529.51,2776.24 ; Jtop4.B18@2557.49,2776.24 Jtop4.B18@2529.51,2776.24
JT35: Jtop1.B17 Jtop2.B17 Jtop3.B17 Jtop4.B17 R1R_IDL_17_12_TerA35.1 R2R_IDL_17_12_TerA35.2 | length 3127.7
  Top Signal w8: Jtop4.B17@2517.2,2689.59 2515.93,2689.59 Jtop4.B17@2529.28,2676.24 2571.76,2718.72 2646.87,2718.72 2694.49,2671.1 2739.97,2671.1 2762.23,2693.36 R1R_IDL_17_12_TerA35.1@2981.11,2693.36 2981.99,2692.49 R2R_IDL_17_12_TerA35.2@2981.99,2638.34 R2R_IDL_17_12_TerA35.2@2973.61,2629.97
  Bot Signal w8: Jtop1.B17@128.79,2682.06 168.72,2682.06 211.2,2724.54 810.71,2724.54 811.13,2724.96 846.32,2724.96 888.8,2682.48 928.72,2682.48 967.98,2721.74 1630.11,2721.74 ; 1630.53,2722.16 1665.73,2722.16 1708.21,2679.68 Jtop3.B17@1748.13,2679.68 ; Jtop3.B17@1728.72,2682.06 1777.65,2730.99 2438.72,2730.99 ; 2439.14,2731.41 2474.33,2731.41 Jtop4.B17@2536.77,2668.97
JT36: Jtop1.B16 Jtop2.B16 Jtop3.B16 Jtop4.B16 R1R_IDL_17_12_TerA36.1 R2R_IDL_17_12_TerA36.2 | length 3009.9
  Top Signal w8: Jtop4.B16@2529.28,2576.24 2571.76,2618.72 2646.87,2618.72 2677.23,2588.36 R1R_IDL_17_12_TerA36.1@2981.11,2588.36 2981.99,2587.49 R2R_IDL_17_12_TerA36.2@2981.99,2533.34 2978.56,2536.77 R2R_IDL_17_12_TerA36.2@2977.36,2535.58
  Bot Signal w8: Jtop1.B16@128.79,2582.06 171.69,2624.96 846.32,2624.96 888.8,2582.48 Jtop2.B16@928.72,2582.48 ; Jtop2.B16@948.2,2579.26 991.1,2622.16 1665.73,2622.16 1708.21,2579.68 Jtop3.B16@1748.13,2579.68 ; Jtop3.B16@1756.8,2588.51 1799.7,2631.41 2474.33,2631.41 Jtop4.B16@2516.81,2588.93
JT37: Jtop1.B15 Jtop2.B15 Jtop3.B15 Jtop4.B15 R1R_IDL_17_12_TerA37.1 R2R_IDL_17_12_TerA37.2 | length 3021.1
  Top Signal w8: Jtop4.B15@2529.28,2476.24 2536.41,2483.36 2576.33,2483.36 2611.68,2518.72 2646.87,2518.72 2677.48,2488.11 2846.98,2488.11 2853.56,2494.68 2872.44,2494.68 2883.76,2483.36 R1R_IDL_17_12_TerA37.1@2981.11,2483.36 2981.11,2429.22 R2R_IDL_17_12_TerA37.2@2981.99,2428.34 R2R_IDL_17_12_TerA37.2@2981.99,2427.77
  Bot Signal w8: Jtop1.B15@128.79,2482.06 171.69,2524.96 846.32,2524.96 888.8,2482.48 Jtop2.B15@928.72,2482.48 ; Jtop2.B15@948.2,2479.26 991.1,2522.16 1665.73,2522.16 1708.21,2479.68 Jtop3.B15@1748.13,2479.68 ; Jtop3.B15@1756.8,2488.51 1790.01,2521.72 2452.74,2521.72 2498.23,2476.24 Jtop4.B15@2529.28,2476.24
JT38: Jtop1.B14 Jtop2.B14 Jtop3.B14 Jtop4.B14 R1R_IDL_17_12_TerA38.1 R2R_IDL_17_12_TerA38.2 | length 3050.6
  Top Signal w8: Jtop4.B14@2529.28,2376.24 2571.76,2418.72 2646.87,2418.72 2687.23,2378.36 R1R_IDL_17_12_TerA38.1@2981.11,2378.36 2981.11,2350.65 2981.99,2349.77 R2R_IDL_17_12_TerA38.2@2981.99,2323.34
  Bot Signal w8: Jtop1.B14@128.79,2382.06 171.69,2424.96 846.32,2424.96 888.8,2382.48 Jtop2.B14@928.72,2382.48 ; Jtop2.B14@948.2,2379.26 991.1,2422.16 1665.73,2422.16 1708.21,2379.68 Jtop3.B14@1748.13,2379.68 ; Jtop3.B14@1756.8,2388.51 1799.7,2431.41 2474.33,2431.41 2516.81,2388.93 2541.98,2388.93 Jtop4.B14@2529.28,2376.24
JT39: Jtop1.B13 Jtop2.B13 Jtop3.B13 Jtop4.B13 R1R_IDL_17_12_TerA39.1 R2R_IDL_17_12_TerA39.2 | length 3064.7
  Top Signal w8: Jtop4.B13@2529.28,2276.24 2571.79,2318.74 2935.73,2318.74 R1R_IDL_17_12_TerA39.1@2981.11,2273.36 2981.11,2245.65 2981.99,2244.77 R2R_IDL_17_12_TerA39.2@2981.99,2218.34
  Bot Signal w8: Jtop1.B13@129.28,2276.24 174.04,2321 867.56,2321 910.21,2278.35 Jtop2.B13@918.19,2278.35 960.67,2320.83 1684.69,2320.83 Jtop3.B13@1729.28,2276.24 1784.08,2331.03 2471.19,2331.03 2520.2,2282.02 2520.2,2276.24 Jtop4.B13@2529.28,2276.24
JT40: Jtop1.B12 Jtop2.B12 Jtop3.B12 Jtop4.B12 R1R_IDL_17_12_TerA40.1 R2R_IDL_17_12_TerA40.2 | length 3086.7
  Top Signal w8: Jtop4.B12@2529.28,2176.24 2572.03,2218.99 2586.89,2218.99 2594.31,2226.41 2657.61,2226.41 2715.66,2168.36 R1R_IDL_17_12_TerA40.1@2981.11,2168.36 2981.99,2167.49 2981.12,2113.36 R2R_IDL_17_12_TerA40.2@2981.11,2112.68
  Bot Signal w8: Jtop1.B12@129.28,2176.24 179.58,2226.54 870,2226.54 Jtop2.B12@918.19,2178.35 968.48,2228.64 1676.88,2228.64 Jtop3.B12@1729.28,2176.24 1747.1,2176.24 1790.82,2219.95 2485.56,2219.95 Jtop4.B12@2529.28,2176.24 Jtop4.B12@2543.7,2176.24
JT41: Jtop1.B3 Jtop2.B3 Jtop3.B3 Jtop4.B3 R1R_IDL_17_12_TerA41.1 R2R_IDL_17_12_TerA41.2 | length 3011.5
  Top Signal w8: Jtop4.B3@2529.28,1276.24 2571.76,1318.72 2867.99,1318.72 2903.87,1282.84 R1R_IDL_17_12_TerA41.1@2987.01,1282.84 2987.01,1255.12 2987.89,1254.25 R2R_IDL_17_12_TerA41.2@2987.89,1227.82
  Bot Signal w8: Jtop1.B3@128.79,1282.06 171.69,1324.96 846.32,1324.96 888.8,1282.48 Jtop2.B3@928.72,1282.48 ; Jtop2.B3@948.2,1279.26 991.1,1322.16 1665.73,1322.16 1708.21,1279.68 Jtop3.B3@1748.13,1279.68 ; Jtop3.B3@1756.8,1288.51 1799.7,1331.41 2474.33,1331.41 Jtop4.B3@2516.81,1288.93
JT42: Jtop1.B2 Jtop2.B2 Jtop3.B2 Jtop4.B2 R1R_IDL_17_12_TerA42.1 R2R_IDL_17_12_TerA42.2 | length 3108.3
  Top Signal w8: Jtop4.B2@2529.28,1176.24 2535.88,1182.84 2575.8,1182.84 2611.68,1218.72 2646.87,1218.72 2700.63,1164.97 2884.15,1164.97 2902.02,1182.84 R1R_IDL_17_12_TerA42.1@2987.01,1182.84 2987.01,1155.12 2987.89,1154.25 R2R_IDL_17_12_TerA42.2@2987.89,1127.82
  Bot Signal w8: Jtop1.B2@129.28,1176.24 180.84,1227.8 884.6,1227.8 918.19,1194.21 Jtop2.B2@918.19,1178.35 960.67,1220.83 1035.79,1220.83 1037.15,1219.46 1686.05,1219.46 Jtop3.B2@1729.28,1176.24 1786.8,1233.76 2471.76,1233.76 Jtop4.B2@2529.28,1176.24 Jtop4.B2@2529.28,1189.3
JT43: Jtop1.B1 Jtop2.B1 Jtop3.B1 Jtop4.B1 R1R_IDL_17_12_TerA43.1 R2R_IDL_17_12_TerA43.2 | length 3099.7
  Top Signal w8: Jtop4.B1@2529.28,1076.24 2572.8,1119.76 2632.87,1119.76 2647.65,1134.53 2912.27,1134.53 R1R_IDL_17_12_TerA43.1@2986.94,1059.87 2986.94,1032.15 2987.81,1031.28 R2R_IDL_17_12_TerA43.2@2987.81,1004.85
  Bot Signal w8: Jtop1.B1@129.28,1076.24 129.28,1084.4 165.71,1120.83 852.17,1120.83 894.66,1078.35 Jtop2.B1@918.19,1078.35 967.64,1127.79 1673.8,1127.79 1725.36,1076.24 Jtop3.B1@1729.28,1076.24 1788.36,1135.32 1810.12,1135.32 1811.68,1133.76 2471.76,1133.76 Jtop4.B1@2529.28,1076.24
JT44: Jtop1.C30 Jtop2.C30 Jtop3.C30 Jtop4.C30 R1R_IDL_17_12_TerA44.1 R2R_IDL_17_12_TerA44.2 | length 2668.4
  Top Signal w8: Jtop1.C30@28.79,3982.06 71.27,4024.54 246.39,4024.54 288.87,3982.06 828.3,3982.06 872.24,4026 1044.44,4026 1070.78,3999.66 ; 1071.2,3999.24 1088.38,3982.06 1628.72,3982.06 1668.82,4022.16 1848.7,4022.16 1888.8,3982.06 Jtop4.C30@2428.72,3982.06 ; Jtop4.C30@2429.28,3976.24 Jtop4.C30@2442.1,3976.24
  Bot Signal w8: R1R_IDL_17_12_TerA44.1@-47.49,4075.36 R2R_IDL_17_12_TerA44.2@-47.49,4017.93 -12.41,4017.93 Jtop1.C30@29.28,3976.24
JT45: Jtop1.C29 Jtop2.C29 Jtop3.C29 Jtop4.C29 R1R_IDL_17_12_TerA45.1 R2R_IDL_17_12_TerA45.2 | length 2653.9
  Top Signal w8: Jtop1.C29@28.79,3882.06 71.27,3924.54 246.39,3924.54 288.87,3882.06 Jtop2.C29@818.19,3882.06 ; Jtop2.C29@818.19,3878.35 858.11,3878.35 900.59,3920.83 935.78,3920.83 943.82,3912.79 992.55,3912.79 1000.59,3920.83 1035.78,3920.83 1036.32,3920.3 1050.99,3920.3 1071.2,3900.08 1071.2,3899.24 1088.38,3882.06 1628.72,3882.06 1665.71,3919.05 1851.81,3919.05 1888.8,3882.06 Jtop4.C29@2428.72,3882.06
  Bot Signal w8: R1R_IDL_17_12_TerA45.1@-46.62,3967.95 -46.62,3940.23 -47.49,3939.36 R2R_IDL_17_12_TerA45.2@-47.49,3912.93 -7.41,3912.93 Jtop1.C29@29.28,3876.24
JT46: Jtop1.C28 Jtop2.C28 Jtop3.C28 Jtop4.C28 R1R_IDL_17_12_TerA46.1 R2R_IDL_17_12_TerA46.2 | length 2700.2
  Top Signal w8: Jtop1.C28@28.79,3782.06 71.27,3824.54 246.39,3824.54 288.87,3782.06 828.3,3782.06 869.72,3823.48 893.18,3823.48 894.79,3821.87 941.58,3821.87 943.2,3823.48 1046.96,3823.48 1088.38,3782.06 1628.72,3782.06 1666.46,3819.8 1705.84,3819.8 1705.88,3819.76 1752.67,3819.76 1752.72,3819.8 1851.06,3819.8 1888.8,3782.06 2428.72,3782.06 2466.07,3819.41
  Bot Signal w8: R1R_IDL_17_12_TerA46.1@-46.62,3862.95 -46.62,3835.23 -47.49,3834.36 R2R_IDL_17_12_TerA46.2@-47.49,3807.93 -2.41,3807.93 Jtop1.C28@29.28,3776.24
JT47: Jtop1.C27 Jtop2.C27 Jtop3.C27 Jtop4.C27 R1R_IDL_17_12_TerA47.1 R2R_IDL_17_12_TerA47.2 | length 2679.5
  Top Signal w8: Jtop1.C27@28.79,3682.06 71.27,3724.54 246.39,3724.54 288.87,3682.06 828.3,3682.06 869.72,3723.48 893.18,3723.48 894.79,3721.87 941.58,3721.87 943.2,3723.48 1046.96,3723.48 1088.38,3682.06 1628.72,3682.06 1668.82,3722.16 1703.48,3722.16 1705.88,3719.76 1752.67,3719.76 1755.08,3722.16 1848.7,3722.16 1888.8,3682.06 Jtop4.C27@2428.72,3682.06
  Bot Signal w8: R1R_IDL_17_12_TerA47.1@-46.62,3759.95 -46.62,3732.23 -47.49,3731.36 R2R_IDL_17_12_TerA47.2@-47.49,3704.93 0.59,3704.93 Jtop1.C27@29.28,3676.24 ; Jtop4.C27@2429.28,3676.24 Jtop4.C27@2458.73,3676.24
JT48: Jtop1.C26 Jtop2.C26 Jtop3.C26 Jtop4.C26 R1R_IDL_17_12_TerA48.1 R2R_IDL_17_12_TerA48.2 | length 2645.9
  Top Signal w8: Jtop1.C26@28.79,3582.06 71.27,3624.54 246.39,3624.54 288.87,3582.06 828.3,3582.06 867.21,3620.97 1049.47,3620.97 1088.38,3582.06 1628.72,3582.06 1668.82,3622.16 1703.48,3622.16 1705.88,3619.76 1752.67,3619.76 1755.08,3622.16 1848.7,3622.16 1888.8,3582.06 Jtop4.C26@2428.72,3582.06
  Bot Signal w8: R1R_IDL_17_12_TerA48.1@-46.62,3656.36 R1R_IDL_17_12_TerA48.1@-46.62,3654.95 -46.62,3600.81 R2R_IDL_17_12_TerA48.2@-47.49,3599.93 5.59,3599.93 Jtop1.C26@29.28,3576.24
JT49: Jtop1.C25 Jtop2.C25 Jtop3.C25 Jtop4.C25 R1R_IDL_17_12_TerA49.1 R2R_IDL_17_12_TerA49.2 | length 2644.5
  Top Signal w8: Jtop1.C25@28.79,3482.06 71.27,3524.54 246.39,3524.54 288.87,3482.06 Jtop2.C25@818.19,3482.06 ; Jtop2.C25@818.19,3478.35 824.58,3478.35 867.06,3520.83 935.78,3520.83 936.52,3520.09 999.86,3520.09 1000.59,3520.83 1049.61,3520.83 1088.38,3482.06 1628.72,3482.06 1668.82,3522.16 1703.48,3522.16 1705.88,3519.76 1752.67,3519.76 1755.08,3522.16 1848.7,3522.16 1888.8,3482.06 Jtop4.C25@2428.72,3482.06
  Bot Signal w8: R1R_IDL_17_12_TerA49.1@-46.62,3549.95 -46.62,3522.23 -47.49,3521.36 R2R_IDL_17_12_TerA49.2@-47.49,3494.93 10.59,3494.93 Jtop1.C25@29.28,3476.24
JT50: Jtop1.C24 Jtop2.C24 Jtop3.C24 Jtop4.C24 R1R_IDL_17_12_TerA50.1 R2R_IDL_17_12_TerA50.2 | length 2652
  Top Signal w8: Jtop1.C24@28.79,3382.06 71.27,3424.54 246.39,3424.54 288.87,3382.06 828.3,3382.06 867.79,3421.55 1048.89,3421.55 1088.38,3382.06 1628.72,3382.06 1668.82,3422.16 1703.48,3422.16 1705.88,3419.76 1752.67,3419.76 1755.08,3422.16 1848.7,3422.16 1888.8,3382.06 Jtop4.C24@2428.72,3382.06
  Bot Signal w8: R1R_IDL_17_12_TerA50.1@-38.78,3437.11 R1R_IDL_17_12_TerA50.1@-46.62,3444.95 -46.62,3417.23 -47.49,3416.36 R2R_IDL_17_12_TerA50.2@-47.49,3389.93 15.59,3389.93 Jtop1.C24@29.28,3376.24
JT51: Jtop1.C23 Jtop2.C23 Jtop3.C23 Jtop4.C23 R1R_IDL_17_12_TerA51.1 R2R_IDL_17_12_TerA51.2 | length 2667.9
  Top Signal w8: Jtop1.C23@28.79,3282.06 71.27,3324.54 246.39,3324.54 288.87,3282.06 828.3,3282.06 867.79,3321.55 1048.89,3321.55 1088.38,3282.06 1628.72,3282.06 1669.1,3322.44 1703.2,3322.44 1705.88,3319.76 1752.67,3319.76 1755.36,3322.44 1848.42,3322.44 1888.8,3282.06 Jtop4.C23@2428.72,3282.06
  Bot Signal w8: R1R_IDL_17_12_TerA51.1@-46.62,3339.95 -46.62,3285.81 R2R_IDL_17_12_TerA51.2@-47.49,3284.93 20.59,3284.93 Jtop1.C23@29.28,3276.24 ; Jtop4.C23@2429.28,3276.24 Jtop4.C23@2457.88,3276.24
JT52: Jtop1.C22 Jtop2.C22 Jtop3.C22 Jtop4.C22 R1R_IDL_17_12_TerA52.1 R2R_IDL_17_12_TerA52.2 | length 2668
  Top Signal w8: Jtop1.C22@28.79,3182.06 71.27,3224.54 246.39,3224.54 288.87,3182.06 828.3,3182.06 867.79,3221.55 1048.89,3221.55 1088.38,3182.06 1628.72,3182.06 1669.1,3222.44 1703.2,3222.44 1705.88,3219.76 1752.67,3219.76 1755.36,3222.44 1848.42,3222.44 1888.8,3182.06 Jtop4.C22@2428.72,3182.06
  Bot Signal w8: R1R_IDL_17_12_TerA52.1@-46.62,3234.95 -46.62,3216.62 -47.49,3215.74 R2R_IDL_17_12_TerA52.2@-47.49,3179.93 25.59,3179.93 Jtop1.C22@29.28,3176.24 ; Jtop4.C22@2429.28,3176.24 Jtop4.C22@2460.09,3176.24
JT53: Jtop1.C21 Jtop2.C21 Jtop3.C21 Jtop4.C21 R1R_IDL_17_12_TerA53.1 R2R_IDL_17_12_TerA53.2 | length 2637.1
  Top Signal w8: Jtop1.C21@28.79,3082.06 71.27,3124.54 246.39,3124.54 288.87,3082.06 828.3,3082.06 868.47,3122.23 894.43,3122.23 894.79,3121.87 941.58,3121.87 941.95,3122.23 1048.21,3122.23 1088.38,3082.06 1628.72,3082.06 1669.1,3122.44 1703.2,3122.44 1705.88,3119.76 1752.67,3119.76 1755.36,3122.44 1848.42,3122.44 1888.8,3082.06 Jtop4.C21@2428.72,3082.06
  Bot Signal w8: R1R_IDL_17_12_TerA53.1@-46.62,3129.95 -46.62,3102.23 -47.49,3101.36 R2R_IDL_17_12_TerA53.2@-47.49,3074.93 27.97,3074.93 Jtop1.C21@29.28,3076.24
JT54: Jtop1.C20 Jtop2.C20 Jtop3.C20 Jtop4.C20 R1R_IDL_17_12_TerA54.1 R2R_IDL_17_12_TerA54.2 | length 2666.8
  Top Signal w8: Jtop1.C20@28.79,2982.06 71.27,3024.54 246.39,3024.54 288.87,2982.06 828.3,2982.06 868.47,3022.23 894.43,3022.23 894.79,3021.87 941.58,3021.87 941.95,3022.23 1048.21,3022.23 1088.38,2982.06 1628.72,2982.06 1669.1,3022.44 1703.2,3022.44 1705.88,3019.76 1752.67,3019.76 1755.36,3022.44 1848.42,3022.44 1888.8,2982.06 Jtop4.C20@2428.72,2982.06
  Bot Signal w8: R1R_IDL_17_12_TerA54.1@-46.62,3024.95 -46.62,2970.81 R2R_IDL_17_12_TerA54.2@-47.49,2969.93 22.97,2969.93 Jtop1.C20@29.28,2976.24 ; Jtop4.C20@2429.28,2976.24 Jtop4.C20@2456.97,2976.24
JT55: Jtop1.C19 Jtop2.C19 Jtop3.C19 Jtop4.C19 R1R_IDL_17_12_TerA55.1 R2R_IDL_17_12_TerA55.2 | length 2642.6
  Top Signal w8: Jtop1.C19@28.79,2882.06 71.27,2924.54 246.39,2924.54 288.87,2882.06 828.3,2882.06 868.47,2922.23 894.43,2922.23 894.79,2921.87 941.58,2921.87 941.95,2922.23 1048.21,2922.23 1088.38,2882.06 1628.72,2882.06 1669.1,2922.44 1703.2,2922.44 1705.88,2919.76 1752.67,2919.76 1755.36,2922.44 1848.42,2922.44 1888.8,2882.06 Jtop4.C19@2428.72,2882.06
  Bot Signal w8: R1R_IDL_17_12_TerA55.1@-46.62,2921.36 R1R_IDL_17_12_TerA55.1@-46.62,2919.95 -46.62,2865.81 R2R_IDL_17_12_TerA55.2@-47.49,2864.93 17.97,2864.93 Jtop1.C19@29.28,2876.24
JT56: Jtop1.C18 Jtop2.C18 Jtop3.C18 Jtop4.C18 R1R_IDL_17_12_TerA56.1 R2R_IDL_17_12_TerA56.2 | length 2669.4
  Top Signal w8: Jtop1.C18@28.79,2782.06 71.27,2824.54 246.39,2824.54 288.87,2782.06 828.3,2782.06 868.47,2822.23 1048.21,2822.23 1088.38,2782.06 1628.72,2782.06 1669.1,2822.44 1848.42,2822.44 1888.8,2782.06 Jtop4.C18@2428.72,2782.06
  Bot Signal w8: R1R_IDL_17_12_TerA56.1@-46.62,2814.95 -46.62,2787.23 -47.49,2786.36 R2R_IDL_17_12_TerA56.2@-47.49,2759.93 12.97,2759.93 Jtop1.C18@29.28,2776.24 ; Jtop4.C18@2429.28,2776.24 Jtop4.C18@2457.93,2776.24
JT57: Jtop1.C17 Jtop2.C17 Jtop3.C17 Jtop4.C17 R1R_IDL_17_12_TerA57.1 R2R_IDL_17_12_TerA57.2 | length 2649.6
  Top Signal w8: Jtop1.C17@28.79,2682.06 71.27,2724.54 246.39,2724.54 288.87,2682.06 828.3,2682.06 868.47,2722.23 894.43,2722.23 894.79,2721.87 941.58,2721.87 941.95,2722.23 1048.21,2722.23 1088.38,2682.06 1628.72,2682.06 1669.1,2722.44 1703.2,2722.44 1705.88,2719.76 1752.67,2719.76 1755.36,2722.44 1848.42,2722.44 1888.8,2682.06 Jtop4.C17@2428.72,2682.06
  Bot Signal w8: R2R_IDL_17_12_TerA57.2@-47.49,2654.93 -47.49,2681.36 -46.62,2682.23 R1R_IDL_17_12_TerA57.1@-46.62,2709.95 -4.43,2709.95 Jtop1.C17@29.28,2676.24
JT58: Jtop1.C16 Jtop2.C16 Jtop3.C16 Jtop4.C16 R1R_IDL_17_12_TerA58.1 R2R_IDL_17_12_TerA58.2 | length 2654.8
  Top Signal w8: Jtop1.C16@28.79,2582.06 71.27,2624.54 246.39,2624.54 288.45,2582.48 828.72,2582.48 828.72,2593.58 860.1,2624.96 1046.32,2624.96 1088.8,2582.48 1609.02,2582.48 1651.08,2624.54 2386.24,2624.54 Jtop4.C16@2428.72,2582.06
  Bot Signal w8: R2R_IDL_17_12_TerA58.2@-47.49,2549.93 -46.62,2550.81 R1R_IDL_17_12_TerA58.1@-46.62,2604.95 0.57,2604.95 Jtop1.C16@29.28,2576.24
JT59: Jtop1.C15 Jtop2.C15 Jtop3.C15 Jtop4.C15 R1R_IDL_17_12_TerA59.1 R2R_IDL_17_12_TerA59.2 | length 2652.9
  Top Signal w8: Jtop1.C15@28.79,2482.06 71.27,2524.54 246.39,2524.54 288.45,2482.48 828.72,2482.48 867.7,2521.47 1049.82,2521.47 1088.8,2482.48 1628.3,2482.48 1628.72,2482.06 1674.37,2527.71 1697.93,2527.71 1705.88,2519.76 1752.67,2519.76 1760.63,2527.71 2383.07,2527.71 Jtop4.C15@2428.72,2482.06
  Bot Signal w8: R2R_IDL_17_12_TerA59.2@-47.49,2444.93 -47.49,2471.36 -46.62,2472.23 R1R_IDL_17_12_TerA59.1@-46.62,2499.95 5.57,2499.95 Jtop1.C15@29.28,2476.24
JT60: Jtop1.C14 Jtop2.C14 Jtop3.C14 Jtop4.C14 R1R_IDL_17_12_TerA60.1 R2R_IDL_17_12_TerA60.2 | length 2661.5
  Top Signal w8: Jtop1.C14@28.79,2382.06 71.27,2424.54 246.39,2424.54 288.45,2382.48 828.72,2382.48 868.24,2422.01 1049.27,2422.01 1088.8,2382.48 1628.3,2382.48 1628.72,2382.06 1672.68,2426.03 1704.88,2426.03 1705.33,2425.58 1752.12,2425.58 1752.56,2426.03 1844.84,2426.03 1888.8,2382.06 Jtop4.C14@2428.72,2382.06
  Bot Signal w8: R2R_IDL_17_12_TerA60.2@-47.49,2339.93 -47.49,2394.07 R1R_IDL_17_12_TerA60.1@-46.62,2394.95 10.57,2394.95 Jtop1.C14@29.28,2376.24 ; Jtop4.C14@2429.28,2376.24 Jtop4.C14@2447.11,2376.24
JT61: Jtop1.C13 Jtop2.C13 Jtop3.C13 Jtop4.C13 R1R_IDL_17_12_TerA61.1 R2R_IDL_17_12_TerA61.2 | length 2674.7
  Top Signal w8: Jtop1.C13@28.79,2282.06 71.27,2324.54 246.39,2324.54 288.45,2282.48 828.72,2282.48 869.51,2323.27 893.39,2323.27 894.79,2321.87 941.58,2321.87 942.99,2323.27 1048.01,2323.27 1088.8,2282.48 1628.3,2282.48 1628.72,2282.06 1672.24,2325.58 1700.06,2325.58 1705.88,2319.76 1752.67,2319.76 1758.5,2325.58 2385.2,2325.58 Jtop4.C13@2428.72,2282.06
  Bot Signal w8: R2R_IDL_17_12_TerA61.2@-47.49,2234.93 -47.49,2289.07 R1R_IDL_17_12_TerA61.1@-46.62,2289.95 15.57,2289.95 Jtop1.C13@29.28,2276.24 ; Jtop4.C13@2429.28,2276.24 Jtop4.C13@2456.04,2276.24
JT62: Jtop1.C12 Jtop2.C12 Jtop3.C12 Jtop4.C12 R1R_IDL_17_12_TerA62.1 R2R_IDL_17_12_TerA62.2 | length 2672.4
  Top Signal w8: Jtop1.C12@28.79,2182.06 71.27,2224.54 246.39,2224.54 288.45,2182.48 828.72,2182.48 867.31,2221.07 1050.21,2221.07 1088.8,2182.48 1628.3,2182.48 1628.72,2182.06 1660.8,2214.14 1693.88,2214.14 1694.11,2213.91 1706.88,2213.91 1711.68,2218.72 1746.87,2218.72 1751.68,2213.91 1806.88,2213.91 1811.68,2218.72 1852.14,2218.72 1888.8,2182.06 Jtop4.C12@2428.72,2182.06
  Bot Signal w8: R2R_IDL_17_12_TerA62.2@-47.49,2126.93 -46.62,2126.93 R1R_IDL_17_12_TerA62.1@-46.62,2181.95 23.57,2181.95 Jtop1.C12@29.28,2176.24 ; Jtop1.C12@29.28,2181.95 Jtop1.C12@41.26,2181.95 ; Jtop4.C12@2429.28,2176.24 Jtop4.C12@2453.93,2176.24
